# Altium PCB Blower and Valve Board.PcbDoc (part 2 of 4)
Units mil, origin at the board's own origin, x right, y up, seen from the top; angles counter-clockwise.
Board outline 4950 x 3450 mil, 4 copper layers (Top Layer, Signal Layer 1, Signal Layer 2, Bottom Layer), stack 64.4 mil thick; 260 components, 151 nets, 912 pads, 417 vias.
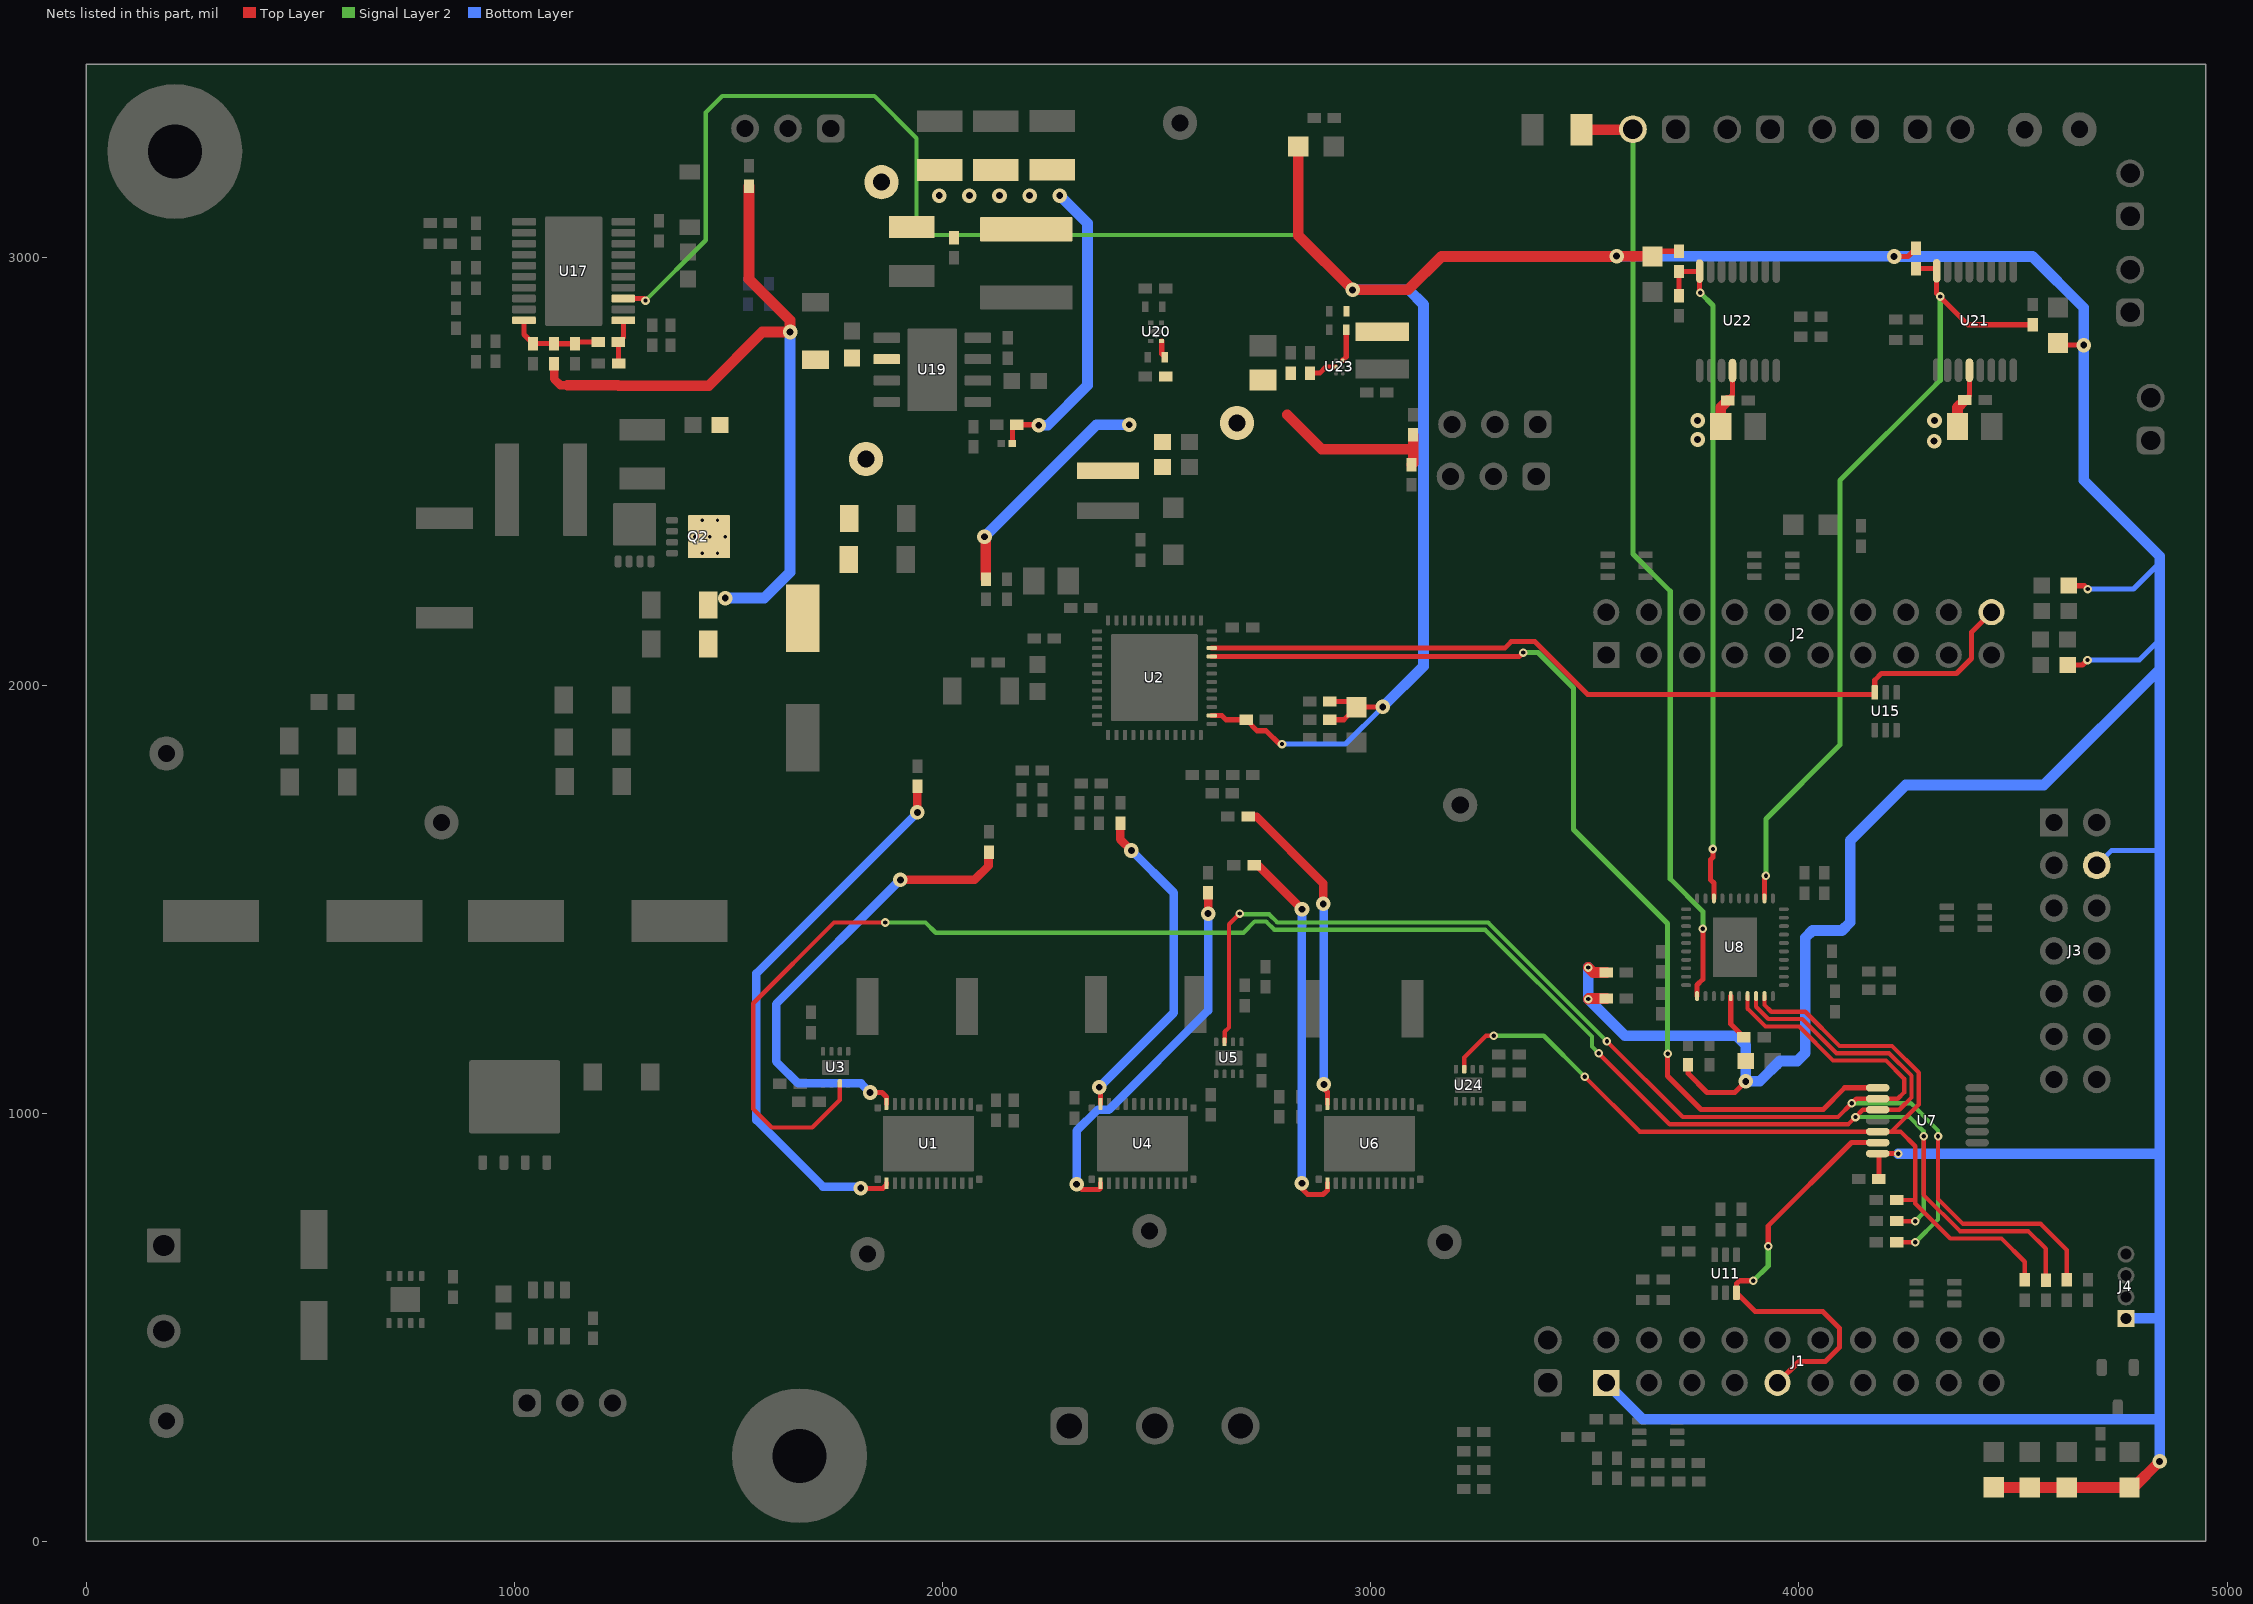
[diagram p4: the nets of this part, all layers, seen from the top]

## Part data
C1 C4 C13 C25 C46 C69: library part CMP-0006297-2, "CAP, CERM, 0.1 uF, 50 V, +/- 10%, X7R, 0402", Cap_Case=0402, Manufacturer=TDK, Supplier Part Number 1=445-5932-1-ND, TempCo=X7R, Tolerance_%=10%, Value1="0.039064 ohm", Value2=50V, ValueDisplayed=0.1uF
C2 C14 C26: library part CMP-0006674-2, "CAP, CERM, 0.01 uF, 50 V, +/- 10%, X7R, 0402", Cap_Case=0402, Manufacturer=MuRata, Supplier Part Number 1=490-4516-1-ND, TempCo=X7R, Tolerance_%=10%, Value1=Unknown, Value2=50V, ValueDisplayed=0.01uF
C3 C47 C48 C67: library part CMP-0008802-2, "CAP, CERM, 10 uF, 50 V, +/- 10%, X7R, 1206", Cap_Case=1206, Manufacturer=Samsung, Supplier Part Number 1=1276-6767-1-ND, TempCo=X7R, Tolerance_%=10%, Value1=Unknown, Value2=50V, ValueDisplayed=10uF
C5 C49 C60: library part CMP-0007508-5, "CAP, CERM, 1 uF, 50 V, +/- 10%, X7R, 0603", Cap_Case=0603, Manufacturer="Taiyo Yuden", Supplier Part Number 1=587-3247-1-ND, TempCo=X7R, Tolerance_%=10%, Value1=Unknown, Value2=50V, ValueDisplayed=1uF
C6 C8 C17 C29 C30: library part CMP-0006219-2, "CAP, CERM, 0.1 uF, 6.3 V, +/- 20%, X5R, 0402", Cap_Case=0402, Manufacturer="Wurth Elektronik", Supplier Part Number 1=732-7478-1-ND, TempCo=X5R, Tolerance_%=20%, Value1=Unknown, Value2=6.3V, ValueDisplayed=0.1uF
C7: library part CMP-0006298-2, "CAP, CERM, 0.047 uF, 50 V, +/- 10%, X7R, 0402", Cap_Case=0402, Manufacturer=TDK, Supplier Part Number 1=445-7336-1-ND, TempCo=X7R, Tolerance_%=10%, Value1="0.06407 ohm", Value2=50V, ValueDisplayed=0.047uF
C9: library part CMP-0006624-2, "CAP, CERM, 1 uF, 6.3 V, +/- 20%, X7R, 0402", Cap_Case=0402, Manufacturer=MuRata, Supplier Part Number 1=490-9665-1-ND, TempCo=X7R, Tolerance_%=20%, Value1=Unknown, Value2=6.3V, ValueDisplayed=1uF
C10 C20 C94: library part CMP-0006658-2, "CAP, CERM, 0.01 uF, 25 V, +/- 10%, X7R, 0402", Cap_Case=0402, Manufacturer=MuRata, Supplier Part Number 1=490-1312-1-ND, TempCo=X7R, Tolerance_%=10%, Value1=Unknown, Value2=25V, ValueDisplayed=0.01uF
C11 C12 C27 C28 C36 C37 C38 C39 C83 C84 C85 C86 C95 C96: library part CMP-0064912-2, "CAP, CERM, 22 pF, 10 V,+/- 5%, C0G/NP0, 0402", Cap_Case=0402, Manufacturer="Wurth Elektronik", Supplier Part Number 1=732-7427-1-ND, TempCo=C0G/NP0, Tolerance_%=5%, Value1=Unknown, Value2=10V, ValueDisplayed=22pF
C15 C16 C18: library part CMP-0006606-2, "CAP, CERM, 1000 pF, 25 V, +/- 10%, X5R, 0402", Cap_Case=0402, Manufacturer=MuRata, Supplier Part Number 1=GRM155R61E102KA01D-ND, TempCo=X5R, Tolerance_%=10%, Value1=Unknown, Value2=25V, ValueDisplayed=1000pF
C19 C35 C91: library part CMP-0006221-2, "CAP, CERM, 0.1 uF, 10 V, +/- 20%, X5R, 0402", Cap_Case=0402, Manufacturer="Wurth Elektronik", Supplier Part Number 1=732-7487-1-ND, TempCo=X5R, Tolerance_%=20%, Value1=Unknown, Value2=10V, ValueDisplayed=0.1uF
C21: library part CMP-0006204-2, "CAP, CERM, 0.1 uF, 16 V, +/- 10%, X5R, 0402", Cap_Case=0402, Manufacturer="Johanson Technology", Supplier Part Number 1=709-1129-1-ND, TempCo=X5R, Tolerance_%=10%, Value1=Unknown, Value2=16V, ValueDisplayed=0.1uF
C22: library part CMP-0007840-2, "CAP, CERM, 4.7 uF, 50 V, +/- 10%, X5R, 0805", Cap_Case=0805, Manufacturer=TDK, Supplier Part Number 1=445-5980-1-ND, TempCo=X5R, Tolerance_%=10%, Value1="0.002346 ohm", Value2=50V, ValueDisplayed=4.7uF
C23 C24: library part CMP-0007005-5, "CAP, CERM, 22 uF, 10 V, +/- 20%, X5R, 0603", Cap_Case=0603, Manufacturer=TDK, Supplier Part Number 1=445-9077-1-ND, TempCo=X5R, Tolerance_%=20%, Value1="0.00371 ohm", Value2=10V, ValueDisplayed=22uF
C31 C32 C33: library part CMP-0006592-2, "CAP, CERM, 2200 pF, 16 V, +/- 10%, X5R, 0402", Cap_Case=0402, Manufacturer=MuRata, Supplier Part Number 1=GRM155R61C222KA01D-ND, TempCo=X5R, Tolerance_%=10%, Value1=Unknown, Value2=16V, ValueDisplayed=2200pF
C34: library part CMP-0007107-5, "CAP, CERM, 10 uF, 6.3 V, +/- 20%, X5R, 0603", Cap_Case=0603, Manufacturer="Samsung Electro-Mechanics", Supplier Part Number 1=490-5527-1-ND, TempCo=X5R, Tolerance_%=20%, Value1=Unknown, Value2=6.3V, ValueDisplayed=10uF
C40: library part CMP-0006589-2, "CAP, CERM, 1000 pF, 16 V, +/- 10%, X5R, 0402", Cap_Case=0402, Manufacturer=MuRata, Supplier Part Number 1=GRM155R61C102KA01D-ND, TempCo=X5R, Tolerance_%=10%, Value1=Unknown, Value2=16V, ValueDisplayed=1000pF
C41: library part CMP-0007482-3, "CAP, CERM, 470 pF, 100 V, +/- 10%, X7R, 0603", Cap_Case=0603, Manufacturer=MuRata, Supplier Part Number 1=490-1467-1-ND, TempCo=X7R, Tolerance_%=10%, Value1=Unknown, Value2=100V, ValueDisplayed=470pF
C42: library part CMP-0011388-2, "CAP, AL, 47 uF, 50 V, +/- 20%, 0.68 ohm, SMD", Cap_Case=F80, Manufacturer=Chemi-Con, Supplier Part Number 1=565-2568-1-ND, Tolerance_%=20%, Value1="0.68 ohm", Value2=50V, ValueDisplayed=47uF
C43 C44: library part CMP-0011243-1, "CAP, AL, 330 uF, 50 V, +/- 20%, SMD", Cap_Case=KE0, Manufacturer=Chemi-Con, Tolerance_%=20%, Value1=Unknown, Value2=50V, ValueDisplayed=330uF
C45: library part CMP-0078149-1, "CAP, AL, 180 µF, 50 V, +/- 20%, 0.34 ohm, AEC-Q200 Grade 2, SMD", Cap_Case=8X10.2mm, Manufacturer=Panasonic, Supplier Part Number 1=P18966CT-ND, Tolerance_%=20%, Value1="0.34 ohm", Value2=50V, ValueDisplayed=180µF
C50 C51 C52 C53 C54 C55 C56 C57: library part CMP-0086153-1, "CAP, CERM, 10 µF, 50 V,+/- 10%, X5R, 1206", Cap_Case=1206, Manufacturer="Taiyo Yuden", TempCo=X5R, Tolerance_%=10%, Value2=50V, ValueDisplayed=10µF
C58: library part CMP-0006230-2, "CAP, CERM, 100 pF, 50 V, +/- 10%, X7R, 0402", Cap_Case=0402, Manufacturer="Wurth Elektronik", Supplier Part Number 1=732-7550-1-ND, TempCo=X7R, Tolerance_%=10%, Value1=Unknown, Value2=50V, ValueDisplayed=100pF
C59: library part CMP-0006614-2, "CAP, CERM, 0.1 uF, 50 V, +/- 20%, X5R, 0402", Cap_Case=0402, Manufacturer=MuRata, Supplier Part Number 1=GRM155R61H104ME14D-ND, TempCo=X5R, Tolerance_%=20%, Value1=Unknown, Value2=50V, ValueDisplayed=0.1uF
C61: library part CMP-0006574-2, "CAP, CERM, 0.033 uF, 10 V, +/- 10%, X5R, 0402", Cap_Case=0402, Manufacturer=MuRata, Supplier Part Number 1=490-5411-1-ND, TempCo=X5R, Tolerance_%=10%, Value1=Unknown, Value2=10V, ValueDisplayed=0.033uF
C62: library part CMP-0006693-2, "CAP, CERM, 560 pF, 50 V, +/- 10%, X7R, 0402", Cap_Case=0402, Manufacturer=MuRata, Supplier Part Number 1=490-1301-1-ND, TempCo=X7R, Tolerance_%=10%, Value1=Unknown, Value2=50V, ValueDisplayed=560pF
C63: library part CMP-0007122-5, "CAP, CERM, 10 uF, 16 V, +/- 20%, X5R, 0603", Cap_Case=0603, Manufacturer="Taiyo Yuden", Supplier Part Number 1=587-3238-1-ND, TempCo=X5R, Tolerance_%=20%, Value1=Unknown, Value2=16V, ValueDisplayed=10uF
C64: library part CMP-0006279-2, "CAP, CERM, 0.1 uF, 50 V, +/- 10%, X5R, 0402", Cap_Case=0402, Manufacturer=TDK, Supplier Part Number 1=445-5942-1-ND, TempCo=X5R, Tolerance_%=10%, Value1="0.039064 ohm", Value2=50V, ValueDisplayed=0.1uF
C65: library part CMP-0006259-2, "CAP, CERM, 0.1 uF, 10 V, +/- 10%, X5R, 0402", Cap_Case=0402, Manufacturer=TDK, Supplier Part Number 1=445-1265-1-ND, TempCo=X5R, Tolerance_%=10%, Value1=Unknown, Value2=10V, ValueDisplayed=0.1uF
C66: library part CMP-0006264-2, "CAP, CERM, 0.33 uF, 10 V, +/- 10%, X5R, 0402", Cap_Case=0402, Manufacturer=TDK, Supplier Part Number 1=445-4987-1-ND, TempCo=X5R, Tolerance_%=10%, Value1=Unknown, Value2=10V, ValueDisplayed=0.33uF
C68: library part CMP-0007047-4, "CAP, CERM, 0.22 uF, 50 V, +/- 10%, X7R, 0603", Cap_Case=0603, Manufacturer=TDK, Supplier Part Number 1=445-7408-1-ND, TempCo=X7R, Tolerance_%=10%, Value1="0.021699 ohm", Value2=50V, ValueDisplayed=0.22uF
C70: library part CMP-0009770-1, "CAP, CERM, 220 pF, 25 V, +/- 10%, X7R, 0201", Cap_Case=0201, Manufacturer=MuRata, Supplier Part Number 1=490-3176-1-ND, TempCo=X7R, Tolerance_%=10%, Value1=Unknown, Value2=25V, ValueDisplayed=220pF
C71 C72 C73 C74: library part CMP-0084059-1, "CAP, CERM, 22 µF, 25 V,+/- 10%, X5R, AEC-Q200 Grade 3, 1210", Cap_Case=1210, Manufacturer=MuRata, TempCo=X5R, Tolerance_%=10%, Value2=25V, ValueDisplayed=22µF
C75: library part CMP-0006608-2, "CAP, CERM, 1 uF, 25 V, +/- 10%, X5R, 0402", Cap_Case=0402, Manufacturer=MuRata, Supplier Part Number 1=490-10017-1-ND, TempCo=X5R, Tolerance_%=10%, Value1=Unknown, Value2=25V, ValueDisplayed=1uF
C76: library part CMP-0081458-1, "CAP, CERM, 1 µF, 16 V,+/- 20%, X5R, 0603", Cap_Case=0603, Manufacturer="Yageo America", TempCo=X5R, Tolerance_%=20%, Value2=16V, ValueDisplayed=1µF
C77 C80 C92 C93: library part CMP-0084008-1, "CAP, CERM, 10 µF, 10 V,+/- 20%, X5R, 0402", Cap_Case=0402, Manufacturer=Yageo, Supplier Part Number 1=311-3480-2-ND, TempCo=X5R, Tolerance_%=20%, Value1="0.001 ohm", Value2=10V, ValueDisplayed=10µF
C78 C79: library part CMP-0006563-2, "CAP, CERM, 1 uF, 10 V, +/- 10%, X5R, 0402", Cap_Case=0402, Manufacturer=MuRata, Supplier Part Number 1=490-3890-1-ND, TempCo=X5R, Tolerance_%=10%, Value1=Unknown, Value2=10V, ValueDisplayed=1uF
C81 C87: library part CMP-0008305-2, "CAP, CERM, 22 uF, 25 V, +/- 20%, X5R, 0805", Cap_Case=0805, Manufacturer=MuRata, Supplier Part Number 1=490-10749-1-ND, TempCo=X5R, Tolerance_%=20%, Value1=Unknown, Value2=25V, ValueDisplayed=22uF
C82 C88: library part CMP-0006659-2, "CAP, CERM, 0.1 uF, 25 V, +/- 10%, X7R, 0402", Cap_Case=0402, Manufacturer=MuRata, Supplier Part Number 1=490-10698-1-ND, TempCo=X7R, Tolerance_%=10%, Value1=Unknown, Value2=25V, ValueDisplayed=0.1uF
C89: library part CMP-0007825-2, "CAP, CERM, 47 uF, 10 V, +/- 20%, X5R, 0805", Cap_Case=0805, Manufacturer=TDK, Supplier Part Number 1=445-8239-1-ND, TempCo=X5R, Tolerance_%=20%, Value1="0.00294 ohm", Value2=10V, ValueDisplayed=47uF
C90: library part CMP-0006268-2, "CAP, CERM, 4.7 uF, 10 V, +/- 10%, X5R, 0402", Cap_Case=0402_065, Manufacturer=TDK, Supplier Part Number 1=445-13820-1-ND, TempCo=X5R, Tolerance_%=10%, Value1="0.003417 ohm", Value2=10V, ValueDisplayed=4.7uF
D1 D6 D7 D9 D10 D11: library part CMP-0002829-3, "LED, Red, SMD", Color=red, Manufacturer=Lite-On, Value1=W, Value2=2V
D2: library part CMP-0028377-2, "Diode, Schottky, 60 V, 1 A, SOD-123F", Manufacturer=Nexperia, Value1=1A, Value2=0.57V
D3: library part CMP-0028625-2, "Diode, Schottky, 100 V, 1 A, SOD-123FL", Manufacturer="ON Semiconductor", Value1=1A, Value2=0.76V
D4 D5 D8: library part CMP-0002830-3, "LED, Green, SMD", Color=green, Manufacturer=Lite-On, Value1=W, Value2=2.1V
H1 H2: library part CMP-0003617-1, "Machine Screw, Round, #4-40 x 1/4, Nylon, Philips panhead", Manufacturer="B&F Fastener Supply", Supplier Part Number 1=H542-ND
H7 H8: library part CMP-0003610-1, "Standoff, Hex, 0.5\"L #4-40 Nylon", Manufacturer=Keystone, Supplier Part Number 1=36-1902C-ND
J1 J2: library part CMP-0075613-1, "Receptacle, 2.54mm, 10x2, Gold, TH", Color=Black, Current_A=6.3A, Manufacturer=Samtec, Voltage_V=550V
J3: library part CMP-0054695-2, "Header (shrouded), 100 mil, 7x2, Gold, TH", Manufacturer="Sullins Connector Solutions", Supplier Part Number 1=S9170-ND
J4: library part CMP-0074999-1, "Header, 50mil, 4x1, Gold, TH", Manufacturer=Preci-Dip, Supplier Part Number 1=1212-1328-ND
J5: library part CMP-0079043-1, "Terminal Block, 5.08mm, 3x1, R/A, TH", Color=Green, Current_A=20A, Manufacturer="Wurth Elektronik", Supplier Part Number 1=732-10996-ND, Voltage_V=300V
J6: library part CMP-0074910-1, "Terminal Block, 5.08 mm, 2x1, Brass, TH", Color=Blue, Current_A=15A, Manufacturer="On-Shore Technology", Supplier Part Number 1=ED1609-ND, Voltage_V=300V
J7 J8 J9 J10 J11 J12 J17 J18: library part CMP-0054794-2, "Header, 2.54 mm, 2x1, Gold, TH", Color=Black, Manufacturer="Wurth Elektronik", Supplier Part Number 1=732-5315-ND
J13 J14 J15 J16: library part CMP-0075407-2, "Header, 100mil, 3x1, Gold, TH", Color=Black, Current_A=6.3A, Manufacturer=Samtec, Supplier Part Number 1=SAM1029-03-ND, Voltage_V=550V
L1: library part CMP-0082329-1, "Inductor, Shielded, 22 µH, 1.7 A, 0.28 ohm, SMD", Manufacturer="Wurth Elektronik", Supplier Part Number 1=732-11664-1-ND, Value1="0.28 ohm", Value2=1.7A, ValueDisplayed=22µH
L2: library part CMP-0061020-2, "Inductor, Shielded, Composite, 4.7 µH, 10.5 A, 0.0144 ohm, AEC-Q200 Grade 1, SMD", Manufacturer=Coilcraft, Value1="0.0144 ohm", Value2=10.5A, ValueDisplayed=4.7uH
L3: library part CMP-0085398-2, "Inductor, Shielded, Composite, 33 µH, 3.6 A, 0.105 ohm, AEC-Q200 Grade 1, SMD", Manufacturer=Coilcraft, Value1="0.105 ohm", Value2=3.6A, ValueDisplayed=33µH
L4: library part CMP-0061137-1, "Inductor, Shielded, Composite, 2.2 uH, 1.6 A, 0.08 ohm, SMD", Manufacturer=Coilcraft, Value1="0.08 ohm", Value2=1.6A, ValueDisplayed=2.2uH
Logo1: library part CMP-0074844-1
Logo2: library part CMP-0074838-1, "Texas Instrument Corporate Signature"
Logo3: library part CMP-0074847-1, "FCC_disclaimer"
Logo4: library part CMP-0074769-1
Q1: library part CMP-0000813-2, "MOSFET, N-CH, 60 V, 172 A, DNK0008A (VSON-CLIP-8)", Alternate Manufacturer=None, Manufacturer="Texas Instruments", Supplier Part Number 1=296-35628-1-ND, Value1=3, Value2="27 nC"
Q2 Q3: library part CMP-0000826-2, "MOSFET, N-CH, 60 V, 35 A, DNH0008A (VSONP-8)", Alternate Manufacturer=None, Manufacturer="Texas Instruments", Supplier Part Number 1=CSD18543Q3A-ND, Value1=0.01, Value2="11.1 nC"
Q4: library part CMP-0000376-2, "Transistor, NPN, 45 V, 0.1 A, SOT-23", Manufacturer="ON Semiconductor", Supplier Part Number 1=BC847CLT1GOSCT-ND, Value1="0.1 A", Value2=800
R1 R2 R11 R23: library part CMP-0026744-1, "RES, 82.0 k, 1%, 0.063 W, 0402", Manufacturer="Yageo America", Power_W=63mW, Supplier Part Number 1=311-82.0KLRCT-ND, TempCo="100 ppm/C", Tolerance_%=1%, Value2=0.063W, Value_Code=82k0, ValueDisplayed=82.0k
R3 R4 R14 R24: library part CMP-0026414-2, "RES, 4.99 k, 1%, 0.063 W, AEC-Q200 Grade 0, 0402", Manufacturer=Vishay-Dale, Power_W=63mW, Supplier Part Number 1=541-4.99KLCT-ND, TempCo="100 ppm/C", Tolerance_%=1%, Value2=0.063W, Value_Code=4k99, ValueDisplayed=4.99k
R5 R15 R25: library part CMP-0015418-2, "RES, 0.01, 1%, 3 W, 2512", Manufacturer=Bourns, Power_W=3W, Supplier Part Number 1=CRA2512-FZ-R010ELFCT-ND, TempCo="75 ppm/C", Tolerance_%=1%, Value_Code=R010, ValueDisplayed=0.01
R6 R17 R72: library part CMP-0026951-5, "RES, 5.1 k, 5%, 0.063 W, AEC-Q200 Grade 0, 0402", Manufacturer=Vishay-Dale, Power_W=63mW, Supplier Part Number 1=541-5.1KJCT-ND, TempCo="200 ppm/C", Tolerance_%=5%, Value2=0.063W, Value_Code=5k10, ValueDisplayed=5.1k
R7 R8 R9 R12 R13 R16: library part CMP-0026749-1, "RES, 10.0, 1%, 0.063 W, 0402", Manufacturer="KOA Speer", Power_W=63mW, Supplier Part Number 1=660-RK73H1ETTP10R0F, TempCo="100 ppm/C", Tolerance_%=1%, Value2=0.063W, Value_Code=10R0, ValueDisplayed=10.0
R10 R19: library part CMP-0025958-3, "RES, 10.0 k, 1%, 0.063 W, AEC-Q200 Grade 0, 0402", Manufacturer=Vishay-Dale, Power_W=63mW, Supplier Part Number 1=541-10.0KLCT-ND, TempCo="100 ppm/C", Tolerance_%=1%, Value2=0.063W, Value_Code=10k0, ValueDisplayed=10.0k
R18 R59 R60 R61 R62 R64 R65 R73: library part CMP-0026934-3, "RES, 470, 5%, 0.063 W, AEC-Q200 Grade 0, 0402", Manufacturer=Vishay-Dale, Power_W=63mW, Supplier Part Number 1=541-470JCT-ND, TempCo="200 ppm/C", Tolerance_%=5%, Value2=0.063W, Value_Code=470R, ValueDisplayed=470
R20 R56: library part CMP-0026753-1, "RES, 100 k, 1%, 0.063 W, AEC-Q200 Grade 0, 0402", Manufacturer="Stackpole Electronics Inc", Power_W=63mW, Supplier Part Number 1=RMCF0402FT100KCT-ND, TempCo="100 ppm/C", Tolerance_%=1%, Value2=0.063W, Value_Code=100k
R21: library part CMP-0026403-2, "RES, 49.9 k, 1%, 0.063 W, AEC-Q200 Grade 0, 0402", Manufacturer=Vishay-Dale, Power_W=63mW, Supplier Part Number 1=541-49.9KLCT-ND, TempCo="100 ppm/C", Tolerance_%=1%, Value2=0.063W, Value_Code=49k9, ValueDisplayed=49.9k
R22: library part CMP-0025978-3, "RES, 11.8 k, 1%, 0.063 W, AEC-Q200 Grade 0, 0402", Manufacturer=Vishay-Dale, Power_W=63mW, Supplier Part Number 1=541-11.8KLCT-ND, TempCo="100 ppm/C", Tolerance_%=1%, Value2=0.063W, Value_Code=11k8, ValueDisplayed=11.8k
R26 R27 R28: library part CMP-0026454-2, "RES, 56.2, 1%, 0.063 W, AEC-Q200 Grade 0, 0402", Manufacturer=Vishay-Dale, Power_W=63mW, Supplier Part Number 1=541-56.2LCT-ND, TempCo="100 ppm/C", Tolerance_%=1%, Value2=0.063W, Value_Code=56R2, ValueDisplayed=56.2
R29 R34: library part CMP-0025953-3, "RES, 102, 1%, 0.063 W, AEC-Q200 Grade 0, 0402", Manufacturer=Vishay-Dale, Power_W=63mW, Supplier Part Number 1=541-102LCT-ND, TempCo="100 ppm/C", Tolerance_%=1%, Value2=0.063W, Value_Code=102R, ValueDisplayed=102
R30 R31 R32 R33: library part CMP-0026918-5, "RES, 3.3 k, 5%, 0.063 W, AEC-Q200 Grade 0, 0402", Manufacturer=Vishay-Dale, Power_W=63mW, Supplier Part Number 1=541-3.3KJCT-ND, TempCo="200 ppm/C", Tolerance_%=5%, Value2=0.063W, Value_Code=3k30, ValueDisplayed=3.3k
R35: library part CMP-0026935-3, "RES, 47 k, 5%, 0.063 W, AEC-Q200 Grade 0, 0402", Manufacturer=Vishay-Dale, Power_W=63mW, Supplier Part Number 1=541-47KJCT-ND, TempCo="200 ppm/C", Tolerance_%=5%, Value2=0.063W, Value_Code=47k0, ValueDisplayed=47k
R36 R37 R38 R39: library part CMP-0022352-4, "RES, 35.7 k, 1%, 0.1 W, AEC-Q200 Grade 0, 0603", Manufacturer=Vishay-Dale, Power_W=100mW, Supplier Part Number 1=541-35.7KHCT-ND, TempCo="100 ppm/C", Tolerance_%=1%, Value2=0.1W, Value_Code=35k7, ValueDisplayed=35.7k
R40: library part CMP-0015840-2, "RES, 0.008, 1%, 2 W, 2512", Manufacturer=Rohm, Power_W=2W, Supplier Part Number 1=RHM.008AUCT-ND, TempCo="100 ppm/C", Tolerance_%=1%, Value_Code=8L000, ValueDisplayed=0.008
R41: library part CMP-0083607-1, "RES, 8.2, 5%, 0.5 W, 1210", Manufacturer=Yageo, Power_W=500mW, TempCo="200 ppm/C", Tolerance_%=5%, Value2=0.5W, Value_Code=8R20, ValueDisplayed=8.2
R42 R49 R50 R74 R75 R76 R77 R78: library part CMP-0081856-1, "RES, 0, 0%, 0.2 W, AEC-Q200 Grade 0, 0402", Manufacturer=Vishay-Dale, Power_W=200mW, Supplier Part Number 1=541-0.0YBTR-ND, Tolerance_%=0%, Value2=0.2W, Value_Code=0
R43: library part CMP-0026718-1, "RES, 49.9 k, 1%, 0.063 W, 0402", Manufacturer=Rohm, Power_W=63mW, Supplier Part Number 1=RHM49.9KLCT-ND, TempCo="100 ppm/C", Tolerance_%=1%, Value2=0.063W, Value_Code=49k9, ValueDisplayed=49.9k
R44: library part CMP-0081725-1, "RES, 39.0 k, 1%, 0.1 W, AEC-Q200 Grade 0, 0402", Manufacturer=Panasonic, Power_W=100mW, Supplier Part Number 1=P39.0KLCT-ND, TempCo="100 ppm/C", Tolerance_%=1%, Value2=0.1W, Value_Code=39k0, ValueDisplayed=39.0k
R45 R46: library part CMP-0025951-3, "RES, 100, 1%, 0.063 W, AEC-Q200 Grade 0, 0402", Manufacturer=Vishay-Dale, Power_W=63mW, Supplier Part Number 1=541-100LCT-ND, TempCo="100 ppm/C", Tolerance_%=1%, Value2=0.063W, Value_Code=100R, ValueDisplayed=100
R47: library part CMP-0860046-1, "RES, 14.0 k, 1%, 0.0625 W, 0402", Manufacturer=Yageo, Power_W=62.5mW, Supplier Part Number 1=311-14.0KLRCT-ND, TempCo="100 ppm/C", Tolerance_%=1%, Value2=0.0625W, Value_Code=14k0, ValueDisplayed=14.0k
R48: library part CMP-0026337-2, "RES, 3.65 k, 1%, 0.063 W, AEC-Q200 Grade 0, 0402", Manufacturer=Vishay-Dale, Power_W=63mW, Supplier Part Number 1=541-3.65KLCT-ND, TempCo="100 ppm/C", Tolerance_%=1%, Value2=0.063W, Value_Code=3k65, ValueDisplayed=3.65k
R51: library part CMP-0026186-2, "RES, 23.2 k, 1%, 0.063 W, AEC-Q200 Grade 0, 0402", Manufacturer=Vishay-Dale, Power_W=63mW, Supplier Part Number 1=541-23.2KLCT-ND, TempCo="100 ppm/C", Tolerance_%=1%, Value2=0.063W, Value_Code=23k2, ValueDisplayed=23.2k
R52: library part CMP-0026009-3, "RES, 140 k, 1%, 0.063 W, AEC-Q200 Grade 0, 0402", Manufacturer=Vishay-Dale, Power_W=63mW, Supplier Part Number 1=541-140KLCT-ND, TempCo="100 ppm/C", Tolerance_%=1%, Value2=0.063W, Value_Code=140k
R53: library part CMP-0026315-2, "RES, 36.5 k, 1%, 0.063 W, AEC-Q200 Grade 0, 0402", Manufacturer=Vishay-Dale, Power_W=63mW, Supplier Part Number 1=541-36.5KLCT-ND, TempCo="100 ppm/C", Tolerance_%=1%, Value2=0.063W, Value_Code=36k5, ValueDisplayed=36.5k
R54 R55 R67 R70 R71: library part CMP-0026823-3, "RES, 100 k, 5%, 0.063 W, AEC-Q200 Grade 0, 0402", Manufacturer=Vishay-Dale, Power_W=63mW, Supplier Part Number 1=541-100KJCT-ND, TempCo="200 ppm/C", Tolerance_%=5%, Value2=0.063W, Value_Code=100k
R57: library part CMP-0026619-3, "RES, 9.09 k, 1%, 0.063 W, AEC-Q200 Grade 0, 0402", Manufacturer=Vishay-Dale, Power_W=63mW, Supplier Part Number 1=541-9.09KLCT-ND, TempCo="100 ppm/C", Tolerance_%=1%, Value2=0.063W, Value_Code=9k09, ValueDisplayed=9.09k
R58 R66: library part CMP-0026825-5, "RES, 10 k, 5%, 0.063 W, AEC-Q200 Grade 0, 0402", Manufacturer=Vishay-Dale, Power_W=63mW, Supplier Part Number 1=541-10KJCT-ND, TempCo="200 ppm/C", Tolerance_%=5%, Value2=0.063W, Value_Code=10k0, ValueDisplayed=10k
R63: library part CMP-0026906-3, "RES, 330, 5%, 0.063 W, AEC-Q200 Grade 0, 0402", Manufacturer=Vishay-Dale, Power_W=63mW, Supplier Part Number 1=541-330JCT-ND, TempCo="200 ppm/C", Tolerance_%=5%, Value2=0.063W, Value_Code=330R, ValueDisplayed=330
R68: library part CMP-0017269-2, "RES, 0.33, 1%, 0.5 W, 1206", Manufacturer="Stackpole Electronics Inc", Power_W=500mW, Supplier Part Number 1=CSR1206FKR330CT-ND, TempCo="100 ppm/C", Tolerance_%=1%, Value2=0.5W, Value_Code=R330, ValueDisplayed=0.33
R69: library part CMP-0026205-1, "RES, 267 k, 1%, 0.063 W, 0402", Manufacturer=Vishay-Dale, Power_W=63mW, Supplier Part Number 1=541-267KLCT-ND, TempCo="100 ppm/C", Tolerance_%=1%, Value2=0.063W, Value_Code=267k
TP2 TP8 TP11 TP13 TP14: library part CMP-0055154-1, "Test Point, Miniature, Blue, TH", Color=Blue, Manufacturer=Keystone, Supplier Part Number 1=36-5117-ND
TP16 TP17 TP18 TP19: library part CMP-0055137-1, "Test Point, Miniature, Red, TH", Color=Red, Manufacturer=Keystone, Supplier Part Number 1=36-5000-ND
TP20 TP21 TP22 TP23: library part CMP-0055138-1, "Test Point, Miniature, Black, TH", Color=Black, Manufacturer=Keystone, Supplier Part Number 1=36-5001-ND
U1 U4 U6: library part CMP-0013348-3, "40 V Half-Bridge NexFE Power Block, DMM0022A (LSON-CLIP-27)", Alternate Manufacturer="Texas Instruments", Alternate PartNumber=CSD88584Q5DCT
U2: library part CMP-0013777-5, "60V Three-Phase Smart Gate Driver With Buck Regulator and Three Current Shunt Amplifiers, RGZ0048A (VQFN-48)", Alternate Manufacturer="Texas Instruments", Alternate PartNumber=DRV8323RSRGZT, Operating Temperature Range="-40 to 125 C", Rating=Catalog
U3 U5 U24: library part CMP-0081592-2, "I2C Compatible Upgrade to Industry Standard LM75 / TMP75 Digital Temperature Sensors, DSG0008A (WSON-8)", Alternate Manufacturer="Texas Instruments", Alternate PartNumber=TMP1075DSGR, Operating Temprature Range="-40 to 125 C", Rating=Catalog
U7: library part CMP-0054473-1, "Dual 4-Input Positive-AND Gates, PW0014A, TUBE", F @ Nom Voltage(Max)(Mhz)=70, Generic Part Number=SN74HC21, ICC @ Nom Voltage(Max)(mA)=0.02, Manufacturer="Texas Instruments", Operating Temperature Range(C)="-40 to 85", Rating=Catalog, tpd @ Nom Voltage(Max)(ns)=28, Voltage(Nom)(V)=5
U8: library part CMP-0084068-1, "24MHz 105C ULP Microcontroller With 32 KB FRAM, 4 KB SRAM, 44 IO, 12-bit ADC, RHA0040E (VQFN-40)", Alternate Manufacturer="Texas Instruments", Alternate PartNumber=MSP430FR2155TRHAT, Operating Temperature Range="-40 to 105 C", Rating=Catalog
U9 U10 U11 U12 U13 U14 U15: library part CMP-0066606-3, "Quad-Channel High-Speed ESD Protection Device, DCK0006A (SOT-SC70-6)", Alternate Manufacturer="Texas Instruments", Operating Temperature Range="-40 to 125 C", Rating=Catalog
U16: library part CMP-0081715-3, "33 V Bidirectional Flat-Clamp Surge Protection Device, DRB0008A (VSON-8)", Alternate Manufacturer="Texas Instruments", Alternate PartNumber=TVS3301DRBT, Operating Temperature Range="-40 to 125 C", Rating=Catalog
U17: library part CMP-0066110-3, "3-65V Wide Vin, Current Mode Synchronous Boost Controller with Multiphase Capability, PWP0020A (HTSSOP-20)", Alternate Manufacturer="Texas Instruments", Alternate PartNumber=LM5122MHE/NOPB, Operating Temperature Range="-40 to 125 C", Rating=Catalog
U18: library part CMP-0079180-1, "Low Iq Always ON Smart Diode Controller, DBV0006A (SOT-23-6)", Alternate Manufacturer="Texas Instruments", Alternate PartNumber=LM74700QDBVRQ1
U19: library part CMP-0013272-2, "SIMPLE SWITCHER 3.8V to 36V 3A/2A Synchronous Step-Down Voltage Regulator, DDA0008J (SOIC-8)", Alternate Manufacturer="Texas Instruments", Alternate PartNumber=LMR33630ADDA
U20: library part CMP-0081013-2, "1-uA IQ, 200-mA, Ultralow IQ Low-Dropout Regulator, DQN0004A (X2SON-4)", Alternate Manufacturer="Texas Instruments"
U21 U22: library part CMP-0079215-1, "Dual H-Bridge Motor Driver, PW0016A (TSSOP-16)", Alternate Manufacturer="Texas Instruments", Alternate PartNumber=DRV8847SPWT
U23: library part CMP-0081436-2, "Ultra low IQ Step Down Converter, YBG0006AJAN (DSBGA-6)", Alternate Manufacturer="Texas Instruments", Operating Temperature Range="-40 to 125 C"
ZZ1: library part CMP-0003616-3
ZZ2: library part CMP-0077236-1
ZZ3: library part CMP-0077237-1
ZZ4: library part CMP-0077238-1

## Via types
v1: diameter 34, hole 16, Top Layer to Bottom Layer, 186 vias
v2: diameter 20, hole 10, Top Layer to Bottom Layer, 125 vias
v3: diameter 19.68, hole 7.87, Top Layer to Bottom Layer, 94 vias
v4: diameter 19.68, hole 7.87, Top Layer to Bottom Layer, tented both sides, 12 vias

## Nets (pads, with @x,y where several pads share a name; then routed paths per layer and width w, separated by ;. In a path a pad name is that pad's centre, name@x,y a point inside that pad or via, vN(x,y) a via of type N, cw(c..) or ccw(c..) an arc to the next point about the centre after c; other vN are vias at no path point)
3.3V: C19.1 C30.1 C34.1 C35.1 C92.1 C93.1 D1.1 D4.1 D6.1 D7.1 D8.1 D9.1 D10.1 D11.1 J1.1 J3.4 J4.1 L4.2 R10.2 R19.2 R30.2 R31.2 R35.1 R36.2 R37.2 R58.2 R66.2 U2.26 U7.14 U8.5 U17.13 U23.A2 | length 15262
  Top Layer w12: U17.13@1254.43,2903.08 1301.15,2903.08 v2(1305.98,2898.26) ; U2.26@2628.59,1928.97 2651.8,1928.97 2661.64,1919.13 C19.1@2708.91,1919.13 2734.49,1893.55 2755.53,1893.55 2786.73,1862.35 v2(2792.64,1862.35) ; R19.2@2904.37,1919.13 2937.05,1919.13 D1.1@2966.39,1948.47 ; R10.2@2904.37,1962.04 2952.82,1962.04 D1.1@2966.39,1948.47 ; U23.A2@2934.52,2758.88 2942.63,2766.99 C93.1@2942.63,2829.85 ; v1(3028.02,1949.26) 2967.17,1949.26 D1.1@2966.39,1948.47 ; D10.1@3658.09,3001.16 3670.35,3013.43 R66.2@3719.84,3013.43 ; R35.1@3741.38,1113.78 3741.38,1093.09 3785.64,1048.83 3850.23,1048.83 v1(3875.98,1074.58) ; U8.5@3840.79,1273.75 3840.79,1208.31 C35.1@3871.43,1177.66 ; C30.1@4187.01,846.46 4187.01,903.03 U7.14@4184.06,905.98 4231.81,905.98 v2(4232.28,905.51) ; v1(4222.44,3001.16) 4254.5,3001.16 R58.2@4273.35,3020.01 ; D9.1@4605.3,2799.14 4610.25,2794.19 v1(4665.35,2794.19) ; R37.2@4627.95,2047.24 4662.57,2047.24 v2(4673.99,2058.67) ; R36.2@4630.18,2232.25 4666.89,2232.25 v2(4674.73,2224.41)
  Top Layer w25: D4.1@2830.64,3257.87 2830.64,3050.27 v1(2957.68,2923.23) 3087.15,2923.23 3165.08,3001.16 v1@3574.17,3001.16 ; v2(3507.87,1266.86) 3509.02,1268.01 R31.2@3549.68,1268.01 ; v2(3507.87,1340.43) 3519.56,1328.74 R30.2@3550,1328.74 ; v1(3574.17,3001.97) 3657.28,3001.97 D10.1@3658.09,3001.16 ; D11.1@4454.95,126.34 4455.31,125.98 D6.1@4539.37,125.98 D7.1@4625.67,125.98 D8.1@4772.36,125.98 4781.5,125.98 v1(4842.52,187.01)
  Signal Layer 2 w10: v2(1305.98,2898.26) 1446.85,3039.13 1446.85,3337.68 1485.15,3375.98 1840.55,3375.98 1938.98,3277.56 1938.98,3080.71 1968.5,3051.18 2829.73,3051.18 v1(2957.68,2923.23)
  Bottom Layer w12: v2(2792.64,1862.35) 2941.12,1862.35 v1(3028.02,1949.26) ; v2(4673.99,2058.67) 4794.89,2058.67 4842.52,2106.3 ; v2(4674.73,2224.41) 4781.32,2224.41 4842.52,2285.61 ; J3.4@4695.67,1579.23 4730.62,1614.17 4842.52,1614.17
  Bottom Layer w25: v1(2957.68,2923.23) 3088.76,2923.23 3123.11,2888.88 3123.11,2044.34 v1(3028.02,1949.26) ; v2(3507.87,1340.43) v2(3507.87,1266.86) 3593.63,1181.1 3854.46,1181.1 3875.98,1159.58 v1(3875.98,1074.58) 3908.24,1074.58 3955.71,1122.05 3996.06,1122.05 4014.95,1140.93 4014.95,1410.21 4031.9,1427.17 4100.53,1427.17 4119.82,1446.46 4119.82,1637.09 4249.72,1766.99 4572.11,1766.99 4842.52,2037.4 ; J1.1@3550,370.47 3635.04,285.43 4842.52,285.43 ; v1(3574.17,3001.97) v1(4222.44,3001.16) 4545.61,3001.16 4665.35,2881.41 v1(4665.35,2794.19) 4665.35,2478.54 4842.52,2301.37 4842.52,2285.61 4842.52,2106.3 4842.52,2037.4 ; v2(4232.28,905.51) 4842.52,905.51 ; J4.1@4763.78,520.97 4841.83,520.97 4842.52,521.65 ; v1(4842.52,187.01) 4842.52,285.43 ; 4842.52,1610.32 4842.52,905.51 ; 4842.52,1614.17 4842.52,2037.4 ; 4842.52,285.43 4842.52,521.65 ; 4842.52,521.65 4842.52,905.51
4.0V: C23.1 C24.1 C77.1 C78.1 C89.1 C90.1 C91.1 L1.2 R21.2 R70.2 R71.2 TP16.1 U20.4 U23.B1 | length 1084.1
  Top Layer w12: U20.4@2511.83,2803.8 2511.83,2773.14 C77.1@2518.83,2766.14 ; C91.1@2858.38,2728.74 2880.72,2728.74 2895.11,2743.13 U23.B1@2918.77,2743.13
  Top Layer w25: v1(2097.8,2346.66) 2101.03,2343.43 R21.2@2101.03,2247.87 ; TP16.1@2686.44,2602.47 TP16.1@2686.44,2635.08 ; 2805.12,2631.65 2885.45,2551.32 3098.96,2551.32 ; R71.2@3095.55,2514.81 3098.96,2518.23 3098.96,2551.32 ; R70.2@3098.96,2584.41 3098.96,2551.32
  Bottom Layer w25: v1(2097.8,2346.66) 2359.4,2608.27 v1(2435.77,2608.27)
12V: C70.1 C71.1 C72.1 C73.1 C74.1 C75.1 C81.1 C82.1 C87.1 C88.1 L3.2 R56.2 TP19.1 U21.12 U22.12 | length 1007.6
  Top Layer w12: C70.1@2162.76,2564.44 2162.76,2597.64 R56.2@2173.39,2608.27 2223.3,2608.27 v1(2224.41,2607.16) ; C82.1@3834.01,2665 3834.01,2666.97 3844.84,2677.8 U22.12@3844.84,2734.88 ; C88.1@4387.52,2665.68 4398.35,2676.5 U21.12@4398.35,2735.56
  Top Layer w25: C81.1@3817.63,2603.78 3817.63,2648.63 C82.1@3834.01,2665 ; C87.1@4370.51,2604.46 4370.51,2648.67 C88.1@4387.52,2665.68
  Bottom Layer w25: v1(2224.41,2607.16) 2245.47,2607.16 2338.6,2700.28 2338.6,3078.57 v1(2273.62,3143.55)
  other v1: 4315.87,2569.88 3763.24,2573.77 3763.24,2618.11 4316.65,2618.11 1992.13,3143.55 2062.5,3143.55 2132.88,3143.55 2203.25,3143.55
14V: C41.1 C45.1 C54.1 C55.1 C56.1 C57.1 C67.1 C68.1 Q2.5 Q2.6 Q2.7 Q2.8 Q2.9 R44.2 R55.2 TP18.1 U19.2 | length 1763
  Top Layer w20: R44.2@1092.52,2750.38 1092.52,2715.23 1107.24,2700.51 1124.39,2700.51 ; 1241.81,2700.51 1242.82,2699.49
  Top Layer w25: 1124.39,2700.51 1241.81,2700.51 ; 1242.82,2699.49 1453.48,2699.49 1578.8,2824.8 v1(1643.7,2824.8) 1643.7,2852.36 1547.7,2948.36 R55.2@1547.7,3165.54
  Bottom Layer w25: v1(1492.12,2203.41) 1583.5,2203.41 1643.7,2263.61 v1(1643.7,2824.8)
  other v3: 1438.68,2308.28 1474.31,2308.28 1420.86,2346.66 1456.49,2346.66 1438.68,2385.05 1474.31,2385.05
  other v4: 1492.12,2346.66
ADSEN: J12.2 R68.2 U8.1 | length 2218.6
  Top Layer w12: U8.1@3762.05,1273.75 3762.05,1299.34 3775.59,1312.88 v2(3775.59,1431.04)
  Top Layer w25: R68.2@3492.13,3297.24 3611.13,3297.24 J12.2@3612.34,3298.45
  Signal Layer 2 w12: J12.2@3612.34,3298.45 3612.34,2306.42 3699.34,2219.42 3699.34,1547.84 3775.59,1471.59 v2(3775.59,1431.04)
ALERT1: R6.1 R61.1 U3.3 U7.10 U8.8 | length 5060
  Top Layer w10: U3.3@1759.84,1069.68 1759.84,1030.99 1695.46,966.61 1601.03,966.61 1557.8,1009.83 1557.8,1256.88 1746.52,1445.59 v2(1865.8,1445.59) ; v2(3532.25,1140.24) 3698.33,974.17 4115.01,974.17 v2(4132.1,991.26) 4149.19,1008.35 U7.10@4184.06,1008.35 4234.42,1008.35 4262.76,1036.68 4262.76,1087.93 4210.29,1140.4 4087.83,1140.4 4007.9,1220.33 3928.34,1220.33 3899.84,1248.83 U8.8@3899.84,1273.75 ; R6.1@4228.13,748.03 v2(4271.65,748.03) ; v2(4291.34,946.54) 4291.34,809.47 4376.05,724.76 4535.43,724.76 4576.77,683.42 R61.1@4576.77,610.38
  Signal Layer 2 w10: v2(1865.8,1445.59) 1960.13,1445.59 1983.93,1421.8 2702.79,1421.8 2728.76,1447.77 2755.6,1447.77 2774.78,1428.59 3267.07,1428.59 3516.54,1179.13 3516.54,1155.96 v2(3532.25,1140.24) ; v2(4132.1,991.26) 4258.33,991.26 4291.34,958.25 v2(4291.34,946.54) 4291.34,767.72 v2(4271.65,748.03)
ALERT2: R17.1 R62.1 U5.3 U7.9 U8.7 | length 3703.3
  Top Layer w10: U5.3@2658.63,1166.71 2658.63,1190.47 2668.74,1200.58 2668.74,1441.48 v2(2693.8,1466.54) ; v2(3551.65,1168.05) 3728.54,991.17 4091.09,991.17 v2(4123.54,1023.62) 4133.86,1033.94 U7.9@4184.06,1033.94 4230.87,1033.94 4245.76,1048.83 4245.76,1080.89 4203.24,1123.4 4079.83,1123.4 4000.59,1202.65 3921.98,1202.65 3880.16,1244.47 U8.7@3880.16,1273.75 ; R17.1@4228.13,698.82 v2(4271.65,698.82) ; v2(4325,946.54) 4325,799.85 4383.09,741.76 4564.86,741.76 4625.67,680.95 R62.1@4625.67,610.71
  Signal Layer 2 w10: v2(2693.8,1466.54) 2695.57,1464.77 2762.64,1464.77 2781.82,1445.59 3274.11,1445.59 v2(3551.65,1168.05) ; v2(4123.54,1023.62) 4261.44,1023.62 4325,960.07 v2(4325,946.54) 4325,752.17 v2(4271.65,698.82)
ALERT3: R72.1 R73.1 U7.12 U8.9 U24.3 | length 2350.7
  Top Layer w10: U24.3@3218.5,1102.95 3218.5,1130.42 3269.19,1181.1 v2(3287.4,1181.1) ; v2(3499.54,1085.67) 3628.05,957.17 U7.12@4184.06,957.17 4216.6,957.17 ; U8.9@3919.53,1273.75 3919.53,1253.18 3935.38,1237.33 4014.95,1237.33 4094.88,1157.4 4217.33,1157.4 4279.76,1094.97 4279.76,1020.32 4216.6,957.17 ; R72.1@4228.13,797.24 4271.65,797.24 ; R73.1@4527.56,610.71 4527.56,653.37 4473.17,707.76 4353.32,707.76 4271.65,789.42 4271.65,797.24 ; 4216.6,957.17 4237.32,957.17 4271.65,922.83 4271.65,797.24
  Signal Layer 2 w10: v2(3287.4,1181.1) 3404.11,1181.1 v2(3499.54,1085.67)
BLEN: U2.33 U7.8 | length 2424.3
  Top Layer w12: U2.33@2628.59,2066.77 3346.54,2066.77 v2(3355.91,2076.14) ; v2(3693.38,1139.11) 3693.38,1086.98 3771.19,1009.17 4056.75,1009.17 4107.11,1059.53 U7.8@4184.06,1059.53
  Signal Layer 2 w12: v2(3355.91,2076.14) 3390.79,2076.14 3473.72,1993.2 3473.72,1663.04 3693.38,1443.39 v2(3693.38,1139.11)
CAL: J2.20 U2.34 U15.6 | length 2014
  Top Layer w12: U2.34@2628.59,2086.45 3312.85,2086.45 3328.02,2101.63 3383.36,2101.63 3506.73,1978.25 4177.17,1978.25 U15.6@4177.17,1983.27 4177.17,2011.64 4192.48,2026.96 4368.02,2026.96 4403.17,2062.11 4403.17,2123.64 J2.20@4450,2170.47
COMP-BST: C62.2 R51.1 U17.11 | length 105.3
  Top Layer w12: R51.1@1242.97,2751.44 1242.97,2800.98 C62.2@1242.82,2801.12 1254.43,2812.73 U17.11@1254.43,2851.9
ENABLE: J1.9 U7.13 U11.3 | length 1040
  Top Layer w12: v2(3893.51,608.74) 3861.28,608.74 3854.33,601.79 U11.3@3854.33,580.79 3898.15,536.97 4055.6,536.97 4094.49,498.09 4094.49,453.43 4061.53,420.47 4000,420.47 J1.9@3950,370.47 ; v2(3928.34,689.16) 3928.34,737.09 4122.82,931.57 U7.13@4184.06,931.57
  Signal Layer 2 w12: v2(3893.51,608.74) 3928.34,643.56 v2(3928.34,689.16)
"FAULT DRV8-1": R58.1 R64.1 U8.22 U21.8 | length 1956.7
  Top Layer w12: U8.22@3919.53,1502.1 3919.53,1551.72 v2(3922.93,1555.12) ; R58.1@4273.35,2972.76 4316.65,2972.76 U21.8@4321.58,2967.84 4321.58,2916.31 v2(4330.05,2907.84) 4328.82,2907.84 4321.34,2915.33 4394.81,2841.86 R64.1@4546.24,2841.86
  Signal Layer 2 w12: v2(3922.93,1555.12) 3922.93,1687.59 4095.58,1860.24 4095.58,2477.77 4320.59,2702.78 4330.05,2712.24 v2(4330.05,2907.84)
"FAULT DRV8-2": R65.1 R66.1 U8.28 U22.8 | length 1588.2
  Top Layer w12: R65.1@3719.84,2910.08 R66.1@3719.84,2966.18 3767.08,2966.18 U22.8@3768.06,2967.17 3768.06,2918.2 v2(3769.69,2916.58) ; v2(3799.21,1617.28) 3799.21,1597.92 3793.66,1592.37 3793.66,1545.59 3801.42,1537.84 U8.28@3801.42,1502.1
  Signal Layer 2 w12: v2(3769.69,2916.58) 3799.21,2887.06 v2(3799.21,1617.28)
FB-BST: C61.1 C62.1 R44.1 R48.2 U17.10 | length 216.9
  Top Layer w12: U17.10@1022.14,2851.9 1022.14,2818.78 R48.2@1043.31,2797.62 R44.1@1092.52,2797.62 1092.71,2797.43 C61.1@1141.7,2797.43 1145.39,2801.12 C62.1@1195.58,2801.12
GHA: R42.2 U1.1 | length 1312.3
  Top Layer w12: v1(1808.58,825.31) 1809.32,824.57 1860.15,824.57 1868.94,833.36 U1.1@1868.94,836.79
  Top Layer w20: v1(1941.19,1702.76) R42.2@1941.19,1763.53
  Bottom Layer w20: v1(1808.58,825.31) 1805.21,828.68 1720.53,828.68 1564.96,984.25 1564.96,1326.52 v1(1941.19,1702.76)
GHB: R75.2 U4.1 | length 896.9
  Top Layer w12: v1(2312.99,834.33) 2325.59,821.74 2365.21,821.74 2368.75,825.28 U4.1@2368.75,836.79
  Top Layer w20: R75.2@2619.97,1514.76 2620.01,1514.72 v1(2620.01,1466.54)
  Bottom Layer w20: v1(2312.99,834.33) 2312.99,959.14 2361.79,1007.94 2387.89,1007.94 2620.01,1240.06 v1(2620.01,1466.54)
GHC: R77.2 U6.1 | length 892.5
  Top Layer w12: v1(2839.16,836.61) 2839.16,823.96 2852.75,810.38 2888.69,810.38 2898.63,820.32 U6.1@2898.63,836.59
  Top Layer w20: R77.2@2727.53,1579.23 2736.63,1579.23 v1(2839.35,1476.51)
  Bottom Layer w20: v1(2839.16,836.61) 2839.16,1437.07 2839.35,1437.26 v1(2839.35,1476.51)
GLA: R74.2 U1.22 | length 1105.2
  Top Layer w12: v1(1830.71,1048.64) 1858.44,1048.64 1868.75,1038.32 U1.22@1868.75,1021.83
  Top Layer w20: v1(1901.23,1545.28) 2074.56,1545.28 2107.19,1577.91 2107.19,1608.92 R74.2@2108.51,1610.24
  Bottom Layer w20: v1(1830.71,1048.64) 1809.66,1069.68 1662.6,1069.68 1610.96,1121.32 1610.96,1255.01 v1(1901.23,1545.28)
GLB: R76.2 U4.22 | length 780.6
  Top Layer w12: v1(2365.93,1060.94) 2368.75,1058.12 U4.22@2368.75,1021.83
  Top Layer w20: R76.2@2415,1677.65 2415,1639.67 v1(2440.89,1613.78)
  Bottom Layer w20: v1(2365.93,1060.94) 2539.71,1234.72 2539.71,1514.96 v1(2440.89,1613.78)
GLC: R78.2 U6.22 | length 759.2
  Top Layer w12: v1(2890.45,1067.38) 2890.45,1057.63 2898.63,1049.45 U6.22@2898.63,1021.63
  Top Layer w20: R78.2@2713.75,1692.91 2733.11,1692.91 2889.05,1536.98 v1(2889.05,1488.96)
  Bottom Layer w20: v1(2889.05,1488.96) 2890.45,1487.57 v1(2890.45,1067.38)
